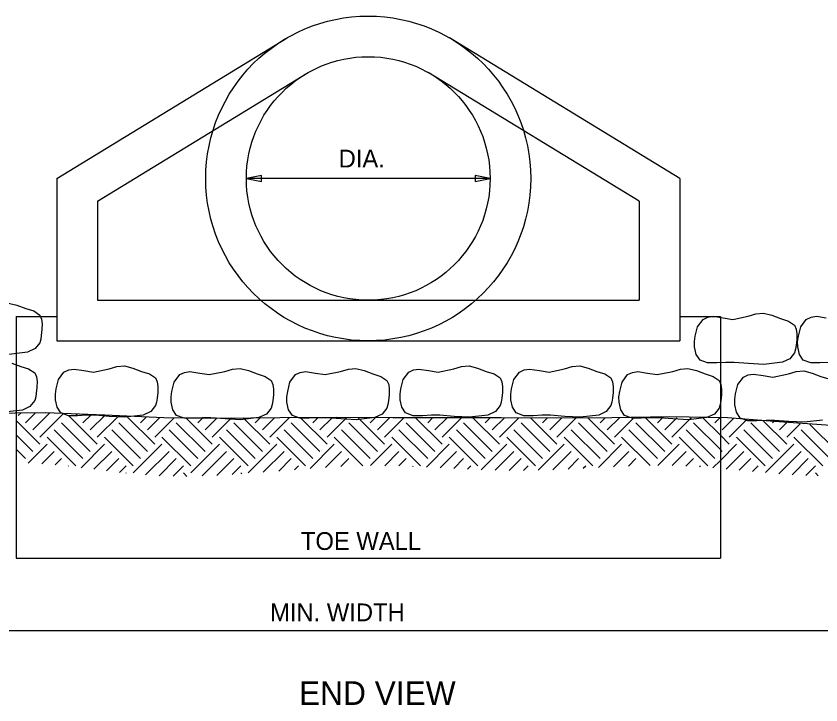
# Model space of a CAD drawing. Extents: x -439.1 to -407.9, y -458.1 to -436.2.
# Drawn here: x -431.65 to -424.86, y -450.95 to -445.13 of the extents above; entities that cross this region are included whole.
import ezdxf

# ---------------------------------------------------------------- set-up
doc = ezdxf.new("R2010")
doc.units = 0
doc.layers.add('Level 4', color=7, linetype='Continuous')

msp = doc.modelspace()

# ---------------------------------------------------------------- linework, layer by layer
at = {"layer": 'Level 4'}
for p, q in [((-431.3081, -446.4994), (-429.3651, -445.3119)), ((-426.0505, -446.4994), (-427.9935, -445.3119)), ((-430.9652, -446.6914), (-429.1868, -445.6045)), ((-426.3934, -446.6914), (-428.173, -445.6045)), ((-431.3081, -446.4994), (-431.3081, -447.8709)), ((-427.6512, -446.4993), (-429.7085, -446.4993)), ((-426.0505, -446.4994), (-426.0505, -447.8709)), ((-430.9652, -446.6914), (-430.9652, -447.528)), ((-426.3934, -446.6914), (-426.3934, -447.528)), ((-430.9652, -447.528), (-426.3934, -447.528)), ((-431.651, -447.6652), (-431.651, -449.7065)), ((-431.651, -447.6652), (-431.3081, -447.6652)), ((-426.0505, -447.6652), (-425.7076, -447.6652)), ((-425.7076, -447.6652), (-425.7076, -449.7065)), ((-431.3081, -447.8709), (-426.0505, -447.8709)), ((-431.6331, -448.502), (-431.6094, -448.4783)), ((-431.5725, -448.5626), (-431.4879, -448.478)), ((-431.5119, -448.6232), (-431.3677, -448.479)), ((-431.4513, -448.6838), (-431.2494, -448.4819)), ((-430.9664, -448.7444), (-431.2088, -448.502)), ((-431.1482, -448.502), (-431.1327, -448.4864)), ((-431.0876, -448.5626), (-431.0167, -448.4917)), ((-431.027, -448.6232), (-430.9012, -448.4975)), ((-430.9664, -448.6838), (-430.7861, -448.5036)), ((-431.4513, -448.7444), (-431.6515, -448.5442)), ((-431.027, -448.8051), (-431.2694, -448.5626)), ((-430.5421, -448.8051), (-430.7845, -448.5626)), ((-430.4815, -448.7444), (-430.7188, -448.5071)), ((-430.6027, -448.5626), (-430.555, -448.5149)), ((-430.5421, -448.6232), (-430.4382, -448.5194)), ((-430.4815, -448.6838), (-430.3183, -448.5207)), ((-430.0571, -448.8051), (-430.2996, -448.5626)), ((-429.9965, -448.7444), (-430.2203, -448.5207)), ((-430.1178, -448.5626), (-430.0759, -448.5207)), ((-430.0571, -448.6232), (-429.9546, -448.5207)), ((-429.9965, -448.6838), (-429.8334, -448.5207)), ((-429.5722, -448.8051), (-429.8147, -448.5626)), ((-429.5116, -448.7444), (-429.7354, -448.5207)), ((-429.6328, -448.5626), (-429.5909, -448.5207)), ((-429.5722, -448.6232), (-429.4697, -448.5207)), ((-429.5116, -448.6838), (-429.3485, -448.5207)), ((-429.0873, -448.8051), (-429.3298, -448.5626)), ((-429.0267, -448.7444), (-429.2505, -448.5207)), ((-429.1479, -448.5626), (-429.106, -448.5207)), ((-429.0873, -448.6232), (-428.9848, -448.5207)), ((-429.0267, -448.6838), (-428.8636, -448.5207)), ((-428.6024, -448.8051), (-428.8449, -448.5626)), ((-428.5418, -448.7444), (-428.7656, -448.5207)), ((-428.663, -448.5626), (-428.6211, -448.5207)), ((-428.6024, -448.6232), (-428.4999, -448.5207)), ((-428.5418, -448.6838), (-428.3787, -448.5207)), ((-428.1175, -448.8051), (-428.36, -448.5626)), ((-428.0569, -448.7444), (-428.2806, -448.5207)), ((-428.1781, -448.5626), (-428.1361, -448.5206)), ((-428.1175, -448.6232), (-428.0147, -448.5204)), ((-428.0569, -448.6838), (-427.8934, -448.5204)), ((-427.6326, -448.8051), (-427.8751, -448.5626)), ((-427.572, -448.7444), (-427.7961, -448.5203)), ((-427.6932, -448.5626), (-427.6511, -448.5205)), ((-427.6326, -448.6232), (-427.5301, -448.5207)), ((-427.572, -448.6838), (-427.4088, -448.5207)), ((-427.1477, -448.8051), (-427.3901, -448.5626)), ((-427.0871, -448.7444), (-427.3108, -448.5207)), ((-427.2083, -448.5626), (-427.1664, -448.5207)), ((-427.1477, -448.6232), (-427.0452, -448.5207)), ((-427.0871, -448.6838), (-426.9239, -448.5207)), ((-426.6628, -448.8051), (-426.9052, -448.5626)), ((-426.6021, -448.7444), (-426.8259, -448.5207)), ((-426.7234, -448.5626), (-426.6815, -448.5207)), ((-426.6628, -448.6232), (-426.5602, -448.5207)), ((-426.6021, -448.6838), (-426.439, -448.5207)), ((-426.1779, -448.8051), (-426.4203, -448.5626)), ((-426.1172, -448.7444), (-426.341, -448.5207)), ((-426.2385, -448.5626), (-426.1966, -448.5207)), ((-426.1779, -448.6232), (-426.0753, -448.5207)), ((-426.1172, -448.6838), (-425.9541, -448.5207)), ((-425.7081, -448.7899), (-425.9354, -448.5626)), ((-425.7081, -448.6686), (-425.8561, -448.5207)), ((-425.7536, -448.5626), (-425.7116, -448.5207)), ((-425.6929, -448.6232), (-425.5938, -448.524)), ((-425.6323, -448.6838), (-425.4807, -448.5322)), ((-425.208, -448.8051), (-425.4505, -448.5626)), ((-425.1474, -448.7444), (-425.3484, -448.5435)), ((-425.2686, -448.5626), (-425.2577, -448.5517)), ((-425.208, -448.6232), (-425.1464, -448.5616)), ((-425.1474, -448.6838), (-425.0342, -448.5706)), ((-431.0876, -448.8657), (-431.33, -448.6232)), ((-430.6027, -448.8657), (-430.8451, -448.6232)), ((-430.1178, -448.8657), (-430.3602, -448.6232)), ((-429.6328, -448.8657), (-429.8753, -448.6232)), ((-429.1479, -448.8657), (-429.3904, -448.6232)), ((-428.663, -448.8657), (-428.9055, -448.6232)), ((-428.1781, -448.8657), (-428.4206, -448.6232)), ((-427.6932, -448.8657), (-427.9357, -448.6232)), ((-427.2083, -448.8657), (-427.4508, -448.6232)), ((-426.7234, -448.8657), (-426.9658, -448.6232)), ((-426.2385, -448.8657), (-426.4809, -448.6232)), ((-425.7536, -448.8657), (-425.996, -448.6232)), ((-425.2686, -448.8657), (-425.5111, -448.6232)), ((-424.7837, -448.8657), (-425.0262, -448.6232)), ((-424.7231, -448.8051), (-424.9518, -448.5764)), ((-431.5119, -448.8051), (-431.6515, -448.6655)), ((-431.1482, -448.9263), (-431.3907, -448.6838)), ((-430.6633, -448.9263), (-430.9058, -448.6838)), ((-430.1784, -448.9263), (-430.4208, -448.6838)), ((-429.6935, -448.9263), (-429.9359, -448.6838)), ((-429.2086, -448.9263), (-429.451, -448.6838)), ((-428.7243, -448.9256), (-428.9661, -448.6838)), ((-428.2387, -448.9263), (-428.4812, -448.6838)), ((-427.7538, -448.9263), (-427.9963, -448.6838)), ((-427.2689, -448.9263), (-427.5114, -448.6838)), ((-426.784, -448.9263), (-427.0265, -448.6838)), ((-426.3011, -448.9242), (-426.5415, -448.6838)), ((-425.8142, -448.9263), (-426.0566, -448.6838)), ((-425.6323, -448.7444), (-425.7081, -448.6686)), ((-425.3293, -448.9263), (-425.5717, -448.6838)), ((-424.8444, -448.9263), (-425.0868, -448.6838)), ((-431.5492, -448.903), (-431.3907, -448.7444)), ((-431.1033, -448.942), (-430.9058, -448.7444)), ((-430.6633, -448.9869), (-430.4208, -448.7444)), ((-430.1784, -448.9869), (-429.9359, -448.7444)), ((-429.6935, -448.9869), (-429.451, -448.7444)), ((-429.1703, -448.9486), (-428.9661, -448.7444)), ((-428.6611, -448.9243), (-428.4812, -448.7444)), ((-428.1882, -448.9364), (-427.9963, -448.7444)), ((-427.7258, -448.9589), (-427.5114, -448.7444)), ((-427.2457, -448.9637), (-427.0265, -448.7444)), ((-426.7376, -448.9405), (-426.5415, -448.7444)), ((-426.2364, -448.9242), (-426.0566, -448.7444)), ((-425.7081, -448.8809), (-425.5717, -448.7444)), ((-425.3258, -448.9835), (-425.0868, -448.7444)), ((-431.5725, -448.8657), (-431.6515, -448.7867)), ((-431.4346, -448.9097), (-431.33, -448.8051)), ((-430.9953, -448.9553), (-430.8451, -448.8051)), ((-430.5586, -449.0034), (-430.3602, -448.8051)), ((-430.0825, -449.0123), (-429.8753, -448.8051)), ((-429.5663, -448.981), (-429.3904, -448.8051)), ((-429.0402, -448.9398), (-428.9055, -448.8051)), ((-428.5406, -448.9251), (-428.4206, -448.8051)), ((-428.0728, -448.9422), (-427.9357, -448.8051)), ((-427.6092, -448.9635), (-427.4508, -448.8051)), ((-427.1205, -448.9598), (-426.9658, -448.8051)), ((-426.6099, -448.934), (-426.4809, -448.8051)), ((-426.1159, -448.9249), (-425.996, -448.8051)), ((-425.6929, -448.8051), (-425.7081, -448.7899)), ((-425.6592, -448.9532), (-425.5111, -448.8051)), ((-425.214, -448.9929), (-425.0262, -448.8051)), ((-431.322, -448.9183), (-431.2694, -448.8657)), ((-430.8877, -448.9689), (-430.7845, -448.8657)), ((-430.4443, -449.0103), (-430.2996, -448.8657)), ((-429.9574, -449.0084), (-429.8147, -448.8657)), ((-429.4343, -448.9702), (-429.3298, -448.8657)), ((-428.9113, -448.9321), (-428.8449, -448.8657)), ((-428.4215, -448.9272), (-428.36, -448.8657)), ((-427.9575, -448.9481), (-427.8751, -448.8657)), ((-427.4897, -448.9653), (-427.3901, -448.8657)), ((-426.9937, -448.9541), (-426.9052, -448.8657)), ((-426.4835, -448.9288), (-426.4203, -448.8657)), ((-425.9993, -448.9296), (-425.9354, -448.8657)), ((-425.7712, -448.9439), (-425.7081, -448.8809)), ((-425.548, -448.9632), (-425.4505, -448.8657)), ((-425.1011, -449.0012), (-424.9656, -448.8657)), ((-431.2117, -448.9292), (-431.2088, -448.9263)), ((-430.7794, -448.9817), (-430.7239, -448.9263)), ((-430.3263, -449.0136), (-430.239, -448.9263)), ((-429.8281, -449.0003), (-429.7541, -448.9263)), ((-429.302, -448.9591), (-429.2692, -448.9263)), ((-428.7857, -448.9277), (-428.7843, -448.9263)), ((-428.3044, -448.9313), (-428.2993, -448.9263)), ((-427.8422, -448.9541), (-427.8144, -448.9263)), ((-427.3695, -448.9663), (-427.3295, -448.9263)), ((-426.8657, -448.9474), (-426.8446, -448.9263)), ((-425.8844, -448.9359), (-425.8748, -448.9263)), ((-425.437, -448.9734), (-425.3899, -448.9263)), ((-424.9867, -449.008), (-424.905, -448.9263)), ((-430.7227, -448.9882), (-430.7239, -448.9869)), ((-430.2102, -449.0156), (-430.239, -448.9869)), ((-429.7459, -448.9951), (-429.7541, -448.9869)), ((-424.8819, -449.01), (-424.905, -448.9869)), ((-431.651, -449.7065), (-425.7076, -449.7065)), ((-421.4299, -450.3206), (-436.1489, -450.3206))]:
    msp.add_line(p, q, dxfattribs=at)
for points in [[(-429.582, -446.473), (-429.7085, -446.4993), (-429.582, -446.5255)], [(-427.7776, -446.5255), (-427.6512, -446.4993), (-427.7776, -446.473)], [(-425.9192, -447.8304), (-425.9008, -447.7518), (-425.8534, -447.6891), (-425.8131, -447.6696), (-425.768, -447.6629), (-425.6852, -447.6752), (-425.6037, -447.6891), (-425.4724, -447.6612), (-425.4074, -447.6424), (-425.3441, -447.6366), (-425.2735, -447.6546), (-425.1996, -447.6826), (-425.1324, -447.7035), (-425.0813, -447.7384), (-425.0669, -447.772), (-425.0616, -447.8107), (-425.0626, -447.8603), (-425.0681, -447.9093), (-425.0729, -447.9415), (-425.0813, -447.9717), (-425.1212, -448.0216), (-425.1847, -448.0517), (-425.3408, -448.0703), (-425.4708, -448.0631), (-425.5906, -448.0539), (-425.6623, -448.054), (-425.7384, -448.0572), (-425.8155, -448.0572), (-425.8797, -448.0342), (-425.912, -447.9852), (-425.9257, -447.9224), (-425.9265, -447.8755), (-425.9192, -447.8304)], [(-431.3132, -448.2764), (-431.2949, -448.1978), (-431.2475, -448.1351), (-431.2071, -448.1156), (-431.1621, -448.1088), (-431.0793, -448.1212), (-430.9978, -448.1351), (-430.8665, -448.1072), (-430.8015, -448.0884), (-430.7382, -448.0825), (-430.6676, -448.1006), (-430.5936, -448.1285), (-430.5265, -448.1494), (-430.4753, -448.1844), (-430.461, -448.218), (-430.4556, -448.2567), (-430.4566, -448.3063), (-430.4622, -448.3553), (-430.467, -448.3875), (-430.4753, -448.4177), (-430.5153, -448.4676), (-430.5787, -448.4976), (-430.7349, -448.5163), (-430.8649, -448.509), (-430.9847, -448.4998), (-431.0564, -448.4999), (-431.1325, -448.5031), (-431.2096, -448.5031), (-431.2738, -448.4801), (-431.306, -448.4312), (-431.3198, -448.3684), (-431.3206, -448.3215), (-431.3132, -448.2764)], [(-428.4038, -448.2764), (-428.3855, -448.1978), (-428.3381, -448.1351), (-428.2977, -448.1156), (-428.2527, -448.1088), (-428.1699, -448.1212), (-428.0884, -448.1351), (-427.9571, -448.1072), (-427.8921, -448.0884), (-427.8288, -448.0825), (-427.7582, -448.1006), (-427.6842, -448.1285), (-427.6171, -448.1494), (-427.5659, -448.1844), (-427.5515, -448.218), (-427.5462, -448.2567), (-427.5472, -448.3063), (-427.5528, -448.3553), (-427.5576, -448.3875), (-427.5659, -448.4177), (-427.6059, -448.4676), (-427.6693, -448.4976), (-427.8255, -448.5163), (-427.9555, -448.509), (-428.0752, -448.4998), (-428.147, -448.4999), (-428.2231, -448.5031), (-428.3002, -448.5031), (-428.3644, -448.4801), (-428.3966, -448.4312), (-428.4104, -448.3684), (-428.4112, -448.3215), (-428.4038, -448.2764)], [(-427.4694, -448.2764), (-427.4511, -448.1978), (-427.4037, -448.1351), (-427.3633, -448.1156), (-427.3183, -448.1088), (-427.2355, -448.1212), (-427.154, -448.1351), (-427.0227, -448.1072), (-426.9577, -448.0884), (-426.8944, -448.0825), (-426.8238, -448.1006), (-426.7498, -448.1285), (-426.6827, -448.1494), (-426.6315, -448.1844), (-426.6171, -448.218), (-426.6118, -448.2567), (-426.6128, -448.3063), (-426.6184, -448.3553), (-426.6232, -448.3875), (-426.6315, -448.4177), (-426.6715, -448.4676), (-426.7349, -448.4976), (-426.8911, -448.5163), (-427.0211, -448.509), (-427.1408, -448.4998), (-427.2126, -448.4999), (-427.2887, -448.5031), (-427.3658, -448.5031), (-427.43, -448.4801), (-427.4622, -448.4312), (-427.476, -448.3684), (-427.4768, -448.3215), (-427.4694, -448.2764)], [(-430.3364, -448.2976), (-430.318, -448.219), (-430.2706, -448.1564), (-430.2303, -448.1368), (-430.1852, -448.1301), (-430.1024, -448.1424), (-430.0209, -448.1564), (-429.8896, -448.1284), (-429.8246, -448.1096), (-429.7613, -448.1038), (-429.6907, -448.1218), (-429.6168, -448.1498), (-429.5496, -448.1707), (-429.4985, -448.2056), (-429.4841, -448.2393), (-429.4788, -448.2779), (-429.4798, -448.3275), (-429.4853, -448.3765), (-429.4901, -448.4087), (-429.4985, -448.4389), (-429.5384, -448.4888), (-429.6019, -448.5189), (-429.758, -448.5375), (-429.888, -448.5303), (-430.0078, -448.5211), (-430.0795, -448.5212), (-430.1556, -448.5244), (-430.2327, -448.5244), (-430.2969, -448.5014), (-430.3292, -448.4524), (-430.3429, -448.3896), (-430.3437, -448.3427), (-430.3364, -448.2976)], [(-429.3595, -448.2976), (-429.3411, -448.219), (-429.2938, -448.1564), (-429.2534, -448.1368), (-429.2083, -448.1301), (-429.1255, -448.1424), (-429.044, -448.1564), (-428.9127, -448.1284), (-428.8477, -448.1096), (-428.7844, -448.1038), (-428.7139, -448.1218), (-428.6399, -448.1498), (-428.5727, -448.1707), (-428.5216, -448.2056), (-428.5072, -448.2393), (-428.5019, -448.2779), (-428.5029, -448.3275), (-428.5084, -448.3765), (-428.5132, -448.4087), (-428.5216, -448.4389), (-428.5615, -448.4888), (-428.625, -448.5189), (-428.7812, -448.5375), (-428.9111, -448.5303), (-429.0309, -448.5211), (-429.1026, -448.5212), (-429.1788, -448.5244), (-429.2559, -448.5244), (-429.32, -448.5014), (-429.3523, -448.4524), (-429.366, -448.3896), (-429.3668, -448.3427), (-429.3595, -448.2976)], [(-426.5563, -448.2976), (-426.5379, -448.219), (-426.4905, -448.1564), (-426.4502, -448.1368), (-426.4051, -448.1301), (-426.3223, -448.1424), (-426.2408, -448.1564), (-426.1095, -448.1284), (-426.0445, -448.1096), (-425.9812, -448.1038), (-425.9106, -448.1218), (-425.8367, -448.1498), (-425.7695, -448.1707), (-425.7184, -448.2056), (-425.704, -448.2393), (-425.6986, -448.2779), (-425.6996, -448.3275), (-425.7052, -448.3765), (-425.71, -448.4087), (-425.7184, -448.4389), (-425.7583, -448.4888), (-425.8218, -448.5189), (-425.9779, -448.5375), (-426.1079, -448.5303), (-426.2277, -448.5211), (-426.2994, -448.5212), (-426.3755, -448.5244), (-426.4526, -448.5244), (-426.5168, -448.5014), (-426.5491, -448.4524), (-426.5628, -448.3896), (-426.5636, -448.3427), (-426.5563, -448.2976)]]:
    msp.add_lwpolyline(points, close=True, dxfattribs=at)
for points in [[(-431.7151, -447.5516), (-431.6445, -447.5697), (-431.5705, -447.5976), (-431.5034, -447.6185), (-431.4522, -447.6535), (-431.4378, -447.6871), (-431.4325, -447.7258), (-431.4335, -447.7754), (-431.4391, -447.8244), (-431.4439, -447.8566), (-431.4522, -447.8868), (-431.4922, -447.9367), (-431.5556, -447.9667), (-431.7118, -447.9854)], [(-424.7916, -448.054), (-424.8677, -448.0572), (-424.9448, -448.0572), (-425.009, -448.0342), (-425.0413, -447.9852), (-425.055, -447.9224), (-425.0558, -447.8755), (-425.0485, -447.8304), (-425.0485, -447.8304), (-425.0301, -447.7518), (-424.9827, -447.6891), (-424.9424, -447.6696), (-424.8973, -447.6629), (-424.8145, -447.6752)], [(-431.687, -448.0581), (-431.613, -448.0861), (-431.5459, -448.1069), (-431.4947, -448.1419), (-431.4803, -448.1755), (-431.475, -448.2142), (-431.476, -448.2638), (-431.4815, -448.3128), (-431.4863, -448.345), (-431.4947, -448.3752), (-431.5346, -448.4251), (-431.5981, -448.4552), (-431.7543, -448.4738)], [(-424.8449, -448.5401), (-425.0011, -448.5587), (-425.131, -448.5515), (-425.2508, -448.5423), (-425.3225, -448.5424), (-425.3987, -448.5456), (-425.4758, -448.5456), (-425.5399, -448.5226), (-425.5722, -448.4736), (-425.5859, -448.4109), (-425.5867, -448.364), (-425.5794, -448.3189), (-425.5794, -448.3189), (-425.561, -448.2403), (-425.5137, -448.1776), (-425.4733, -448.158), (-425.4282, -448.1513), (-425.3454, -448.1636), (-425.2639, -448.1776), (-425.1326, -448.1497), (-425.0676, -448.1309), (-425.0043, -448.125), (-424.9338, -448.143), (-424.8598, -448.171), (-424.7926, -448.1919)], [(-424.7758, -448.5844), (-425.2111, -448.5559), (-425.6465, -448.5207), (-426.1347, -448.5123), (-426.6234, -448.5207), (-427.0906, -448.5227), (-427.5578, -448.5207), (-428.0144, -448.5204), (-428.471, -448.5207), (-428.9488, -448.5196), (-429.4266, -448.5207), (-429.9151, -448.5253), (-430.4035, -448.5207), (-430.9026, -448.4974), (-431.4016, -448.4782), (-431.9218, -448.485)]]:
    msp.add_lwpolyline(points, dxfattribs=at)
for radius in [1.3715, 1.0287]:
    msp.add_circle((-428.6798, -446.4993), radius, dxfattribs=at)

# ---------------------------------------------------------------- texts
for s, height, p in [('DIA.', 0.15, (-428.9296, -446.4065)), ('TOE WALL', 0.15, (-429.248, -449.6367)), ('MIN. WIDTH', 0.15, (-429.5082, -450.2392)), ('END VIEW', 0.2, (-429.2642, -450.9458))]:
    msp.add_text(s, height=height, dxfattribs=at).set_placement(p)

doc.saveas('drawing.dxf')
